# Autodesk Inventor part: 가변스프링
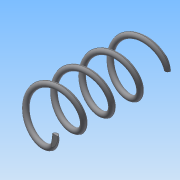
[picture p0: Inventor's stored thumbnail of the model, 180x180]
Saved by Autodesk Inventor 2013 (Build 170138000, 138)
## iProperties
Created: 2015-09
Part Number: 가변스프링
Material: 일반
Document SubType Name: Modeling
Designer: Administrator
Density: 1 g/cm^3
Mass: 0.625242 g
Surface Area: 12.7485 cm^2
Volume: 0.625242 cm^3
Author: Administrator
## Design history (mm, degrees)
sketch "스케치1"
  geometry: L1 (0, 0)-(0, -42); L2 (0, -42)-(8, -42); L3 (0, 0)-(-8, 0); C1 r 1 at (8, 0)
  constraints: 7 end point, 1 centre point, 1 horizontal alignment, 1 parallel, 1 perpendicular, 1 vertical
  dimensions: "d0" = 42 distance of L1.end L1.start (derived); "d1" = 2 diameter of C1; "d2" = 16 diameter of C1.centre L1; "d3" = 8 distance of L1.start L3.end; "d4" = 8 distance of L1.end L2.end
feature "코일1" sketch "스케치1" pitch "d5" = 10; turns "d7" = 4; dims "d6" = 42 (= d0), "d8" = 0, angle "d9" = 90 deg, angle "d10" = 90 deg, "d11" = 0, "d12" = 0
sketch "스케치2"
  geometry: L1 (-42, 9)-(0, 9); L2 (0, 9)-(0, -9); L3 (0, -9)-(-42, -9); L4 (-42, -9)-(-42, 9); 2 further points
  constraints: 8 end point, 2 parallel, 1 coincident, 1 horizontal, 1 midpoint, 1 perpendicular
  dimensions: "d13" = 18 distance of L3.end L1.start; "d15" = 42 distance of L2.end L3.end (derived)
extrude "돌출1" sketch "스케치2" stored distance "d16" = 0; taper "d17" = 0 deg
node "솔리드1"
